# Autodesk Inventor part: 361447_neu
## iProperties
Company: Mayer & Müller AG Schaltgeräte
Created: 2006-10
Part Number: 361447_neu
Material: 1.0120.02
Description: Lasche
Document SubType Name: Modeling
Designer: Natti_01
Density: 7.84 g/cm^3
Mass: 95.9973 g
Surface Area: 77.8369 cm^2
Volume: 12.2446 cm^3
HalbzeugNorm: DIN 174
Zweck: 266360
Abmessung: Fl. 25x4
Author: Natti_01
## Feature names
1. Extrusion3
